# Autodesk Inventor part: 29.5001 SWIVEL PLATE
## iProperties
Created: 2007-07
Part Number: 29.5001 SWIVEL PLATE
Material: Steel
Document SubType Name: Modeling
Designer: Andy Moles
Density: 7.85 g/cm^3
Mass: 325.898 g
Surface Area: 235.596 cm^2
Volume: 41.5157 cm^3
Author: Andy Moles
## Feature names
1. Base1
